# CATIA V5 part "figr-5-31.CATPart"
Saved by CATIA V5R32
Part number: Part1
Bounding box of the stored display mesh (mm): x -32.491 to 32.491, y -32.393 to 32.5, z 0 to 85.656
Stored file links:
  D:\PROJECTS\Project 2022\CATIA V5 6R 2022\Resources\Part Files\c05_catia_v5_6r2022_prt\figr-5-31.CATPart
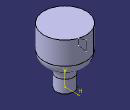
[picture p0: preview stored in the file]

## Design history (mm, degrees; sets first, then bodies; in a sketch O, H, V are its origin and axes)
Body1 (main body)
  Sketch1 on yz-plane, origin (0, 0, 0), H (0, 1, 0), V (0, 0, 1)
    axis line L1 (0, 0) -> (0, 100.0993)
    line L2 (0, 0) -> (13.3295, 0)
    line L3 (13.3295, 0) -> (13.3295, 19.6564)
    arc A1 centre (31.7623, 19.6564) radius 18.4328 from (13.3295, 19.6564) to (23.518, 36.1427) cw
    arc A2 centre (16.25, 50.6768) radius 16.25 from (23.518, 36.1427) to (32.5, 50.6768) ccw
    line L4 (32.5, 50.6768) -> (32.5, 85.6563)
    line L5 (32.5, 85.6563) -> (0, 85.6563)
    point P9 (0, 85.6563)
    line L6 (0, 85.6563) -> (0, 0)
    radius about axis L4 L1 = 32.5
    vertical: L1 V, L3 V, L4 V
    horizontal: L2 H, L5 H
    tangency: A1 L3, A2 L1, A2 A1, L4 A2, L6 A2
    coincidence: P9 L1
  Shaft1: profile Sketch1, axis Sketch1.L1, angle 360
  Sketch2 on yz-plane, origin (0, 0, 0), H (0, 1, 0), V (0, 0, 1)
    axis line L1 (0, 0) -> (0, 91.1904)
    point P1 (0, 0)
    point P2 (0, 91.1904)
    line L2 (32.5, 78.7512) -> (21.4593, 75.7196)
    line L3 (21.4593, 75.7196) -> (21.4593, 66.4534)
    line L4 (21.4593, 66.4534) -> (32.5, 63.9927)
    line L5 (32.5, 63.9927) -> (32.5, 78.7512)
    coincidence: P1 H, P2 V
    vertical: L1 V, L3 V, L5 V
  Groove1: profile Sketch2, axis Sketch2.L1, angle 360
